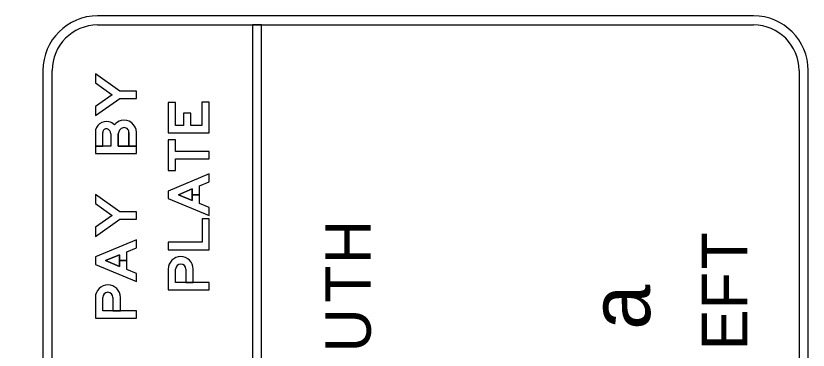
# Model space of a CAD drawing. Extents: x -830008.4 to -829992.7, y 1290284.1 to 1290294.4.
# Drawn here: x -829998.98 to -829998.11, y 1290293.064 to 1290293.43 of the extents above; entities that cross this region are included whole.
import ezdxf

# ---------------------------------------------------------------- set-up
doc = ezdxf.new("R2010")
doc.units = 0
doc.layers.add('SignPanel', color=7, linetype='Continuous')
doc.layers.add('TextLabel', color=7, linetype='Continuous')

msp = doc.modelspace()

# ---------------------------------------------------------------- linework, layer by layer
at = {"layer": 'SignPanel'}
for p, q in [((-829998.17015, 1290293.43038), (-829998.89015, 1290293.43038)), ((-829998.89015, 1290293.42038), (-829998.17015, 1290293.42038)), ((-829998.71015, 1290293.42038), (-829998.72015, 1290293.42038)), ((-829998.72015, 1290293.42038), (-829998.72015, 1290292.51038)), ((-829998.71015, 1290292.51038), (-829998.71015, 1290293.42038)), ((-829998.95015, 1290293.37038), (-829998.95015, 1290292.56038)), ((-829998.94015, 1290292.56038), (-829998.94015, 1290293.37038)), ((-829998.12015, 1290293.37038), (-829998.12015, 1290292.56048)), ((-829998.11015, 1290292.56048), (-829998.11015, 1290293.37038)), ((-829998.84765, 1290293.27947), (-829998.84765, 1290293.30265)), ((-829998.80455, 1290293.13798), (-829998.80455, 1290293.1526)), ((-829998.80455, 1290293.13798), (-829998.80455, 1290293.1526)), ((-829998.80455, 1290293.13798), (-829998.80455, 1290293.1526)), ((-829998.7852, 1290293.13798), (-829998.7852, 1290293.1526)), ((-829998.88455, 1290293.10698), (-829998.88455, 1290293.1216)), ((-829998.88455, 1290293.10698), (-829998.88455, 1290293.1216)), ((-829998.88455, 1290293.10698), (-829998.88455, 1290293.1216)), ((-829998.8652, 1290293.10698), (-829998.8652, 1290293.1216))]:
    msp.add_line(p, q, dxfattribs=at)
for points in [[(-829998.86588, 1290293.34798), (-829998.89265, 1290293.36688), (-829998.89265, 1290293.35696), (-829998.87419, 1290293.34393), (-829998.89265, 1290293.33089), (-829998.89265, 1290293.32098), (-829998.86588, 1290293.33988), (-829998.84765, 1290293.33988), (-829998.84765, 1290293.34798)], [(-829998.86588, 1290293.34798), (-829998.89265, 1290293.36688), (-829998.89265, 1290293.35696), (-829998.87419, 1290293.34393), (-829998.89265, 1290293.33089), (-829998.89265, 1290293.32098), (-829998.86588, 1290293.33988), (-829998.84765, 1290293.33988), (-829998.84765, 1290293.34798)], [(-829998.86588, 1290293.34798), (-829998.89265, 1290293.36688), (-829998.89265, 1290293.35696), (-829998.87419, 1290293.34393), (-829998.89265, 1290293.33089), (-829998.89265, 1290293.32098), (-829998.86588, 1290293.33988), (-829998.84765, 1290293.33988), (-829998.84765, 1290293.34798)], [(-829998.77575, 1290293.33588), (-829998.77575, 1290293.31023), (-829998.78786, 1290293.31023), (-829998.78786, 1290293.3235), (-829998.79596, 1290293.3235), (-829998.79596, 1290293.31023), (-829998.80455, 1290293.31023), (-829998.80455, 1290293.3352), (-829998.81265, 1290293.3352), (-829998.81265, 1290293.30213), (-829998.76765, 1290293.30213), (-829998.76765, 1290293.33588)], [(-829998.77575, 1290293.33588), (-829998.77575, 1290293.31023), (-829998.78786, 1290293.31023), (-829998.78786, 1290293.3235), (-829998.79596, 1290293.3235), (-829998.79596, 1290293.31023), (-829998.80455, 1290293.31023), (-829998.80455, 1290293.3352), (-829998.81265, 1290293.3352), (-829998.81265, 1290293.30213), (-829998.76765, 1290293.30213), (-829998.76765, 1290293.33588)], [(-829998.77575, 1290293.33588), (-829998.77575, 1290293.31023), (-829998.78786, 1290293.31023), (-829998.78786, 1290293.3235), (-829998.79596, 1290293.3235), (-829998.79596, 1290293.31023), (-829998.80455, 1290293.31023), (-829998.80455, 1290293.3352), (-829998.81265, 1290293.3352), (-829998.81265, 1290293.30213), (-829998.76765, 1290293.30213), (-829998.76765, 1290293.33588)], [(-829998.80455, 1290293.26076), (-829998.80455, 1290293.27358), (-829998.76765, 1290293.27358), (-829998.76765, 1290293.28168), (-829998.80455, 1290293.28168), (-829998.80455, 1290293.29451), (-829998.81265, 1290293.29451), (-829998.81265, 1290293.26076)], [(-829998.80455, 1290293.26076), (-829998.80455, 1290293.27358), (-829998.76765, 1290293.27358), (-829998.76765, 1290293.28168), (-829998.80455, 1290293.28168), (-829998.80455, 1290293.29451), (-829998.81265, 1290293.29451), (-829998.81265, 1290293.26076)], [(-829998.80455, 1290293.26076), (-829998.80455, 1290293.27358), (-829998.76765, 1290293.27358), (-829998.76765, 1290293.28168), (-829998.80455, 1290293.28168), (-829998.80455, 1290293.29451), (-829998.81265, 1290293.29451), (-829998.81265, 1290293.26076)], [(-829998.77823, 1290293.2245), (-829998.77823, 1290293.24395), (-829998.76765, 1290293.24839), (-829998.76765, 1290293.25718), (-829998.81265, 1290293.23828), (-829998.81265, 1290293.23018), (-829998.76765, 1290293.21128), (-829998.76765, 1290293.22006)], [(-829998.78633, 1290293.24055), (-829998.78633, 1290293.23423), (-829998.77823, 1290293.23423), (-829998.77823, 1290293.24395), (-829998.76765, 1290293.24839), (-829998.76765, 1290293.25718), (-829998.81265, 1290293.23828), (-829998.81265, 1290293.23018), (-829998.76765, 1290293.21128), (-829998.76765, 1290293.22006), (-829998.77823, 1290293.2245), (-829998.77823, 1290293.23423), (-829998.78633, 1290293.23423), (-829998.78633, 1290293.2279), (-829998.80138, 1290293.23423)], [(-829998.78633, 1290293.24055), (-829998.78633, 1290293.23423), (-829998.77823, 1290293.23423), (-829998.77823, 1290293.24395), (-829998.76765, 1290293.24839), (-829998.76765, 1290293.25718), (-829998.81265, 1290293.23828), (-829998.81265, 1290293.23018), (-829998.76765, 1290293.21128), (-829998.76765, 1290293.22006), (-829998.77823, 1290293.2245), (-829998.77823, 1290293.23423), (-829998.78633, 1290293.23423), (-829998.78633, 1290293.2279), (-829998.80138, 1290293.23423)], [(-829998.78633, 1290293.24055), (-829998.80138, 1290293.23423), (-829998.78633, 1290293.2279)], [(-829998.86588, 1290293.21557), (-829998.89265, 1290293.23447), (-829998.89265, 1290293.22456), (-829998.87419, 1290293.21152), (-829998.89265, 1290293.19849), (-829998.89265, 1290293.18857), (-829998.86588, 1290293.20747), (-829998.84765, 1290293.20747), (-829998.84765, 1290293.21557)], [(-829998.86588, 1290293.21557), (-829998.89265, 1290293.23447), (-829998.89265, 1290293.22456), (-829998.87419, 1290293.21152), (-829998.89265, 1290293.19849), (-829998.89265, 1290293.18857), (-829998.86588, 1290293.20747), (-829998.84765, 1290293.20747), (-829998.84765, 1290293.21557)], [(-829998.86588, 1290293.21557), (-829998.89265, 1290293.23447), (-829998.89265, 1290293.22456), (-829998.87419, 1290293.21152), (-829998.89265, 1290293.19849), (-829998.89265, 1290293.18857), (-829998.86588, 1290293.20747), (-829998.84765, 1290293.20747), (-829998.84765, 1290293.21557)], [(-829998.76765, 1290293.20769), (-829998.77553, 1290293.20769), (-829998.77553, 1290293.18204), (-829998.81265, 1290293.18204), (-829998.81265, 1290293.17394), (-829998.76765, 1290293.17394)], [(-829998.76765, 1290293.20769), (-829998.77553, 1290293.20769), (-829998.77553, 1290293.18204), (-829998.81265, 1290293.18204), (-829998.81265, 1290293.17394), (-829998.76765, 1290293.17394)], [(-829998.76765, 1290293.20769), (-829998.77553, 1290293.20769), (-829998.77553, 1290293.18204), (-829998.81265, 1290293.18204), (-829998.81265, 1290293.17394), (-829998.76765, 1290293.17394)], [(-829998.85823, 1290293.15223), (-829998.85823, 1290293.17167), (-829998.84765, 1290293.17611), (-829998.84765, 1290293.1849), (-829998.89265, 1290293.166), (-829998.89265, 1290293.1579), (-829998.84765, 1290293.139), (-829998.84765, 1290293.14779)], [(-829998.86633, 1290293.16827), (-829998.86633, 1290293.16195), (-829998.85823, 1290293.16195), (-829998.85823, 1290293.17167), (-829998.84765, 1290293.17611), (-829998.84765, 1290293.1849), (-829998.89265, 1290293.166), (-829998.89265, 1290293.1579), (-829998.84765, 1290293.139), (-829998.84765, 1290293.14779), (-829998.85823, 1290293.15223), (-829998.85823, 1290293.16195), (-829998.86633, 1290293.16195), (-829998.86633, 1290293.15563), (-829998.88138, 1290293.16195)], [(-829998.86633, 1290293.16827), (-829998.86633, 1290293.16195), (-829998.85823, 1290293.16195), (-829998.85823, 1290293.17167), (-829998.84765, 1290293.17611), (-829998.84765, 1290293.1849), (-829998.89265, 1290293.166), (-829998.89265, 1290293.1579), (-829998.84765, 1290293.139), (-829998.84765, 1290293.14779), (-829998.85823, 1290293.15223), (-829998.85823, 1290293.16195), (-829998.86633, 1290293.16195), (-829998.86633, 1290293.15563), (-829998.88138, 1290293.16195)], [(-829998.86633, 1290293.16827), (-829998.88138, 1290293.16195), (-829998.86633, 1290293.15563)]]:
    msp.add_lwpolyline(points, close=True, dxfattribs=at)
for points in [[(-829998.89265, 1290293.30265), (-829998.89265, 1290293.27947), (-829998.84765, 1290293.27947)], [(-829998.89265, 1290293.30265), (-829998.89265, 1290293.28758), (-829998.88455, 1290293.28758), (-829998.88455, 1290293.30265)], [(-829998.89265, 1290293.30265), (-829998.89265, 1290293.28758), (-829998.88455, 1290293.28758), (-829998.88455, 1290293.30265)], [(-829998.87555, 1290293.30091), (-829998.87555, 1290293.28757), (-829998.89265, 1290293.28757), (-829998.89265, 1290293.27947), (-829998.84765, 1290293.27947), (-829998.84765, 1290293.28757)], [(-829998.87555, 1290293.30091), (-829998.87555, 1290293.28757), (-829998.89265, 1290293.28757), (-829998.89265, 1290293.27947), (-829998.84765, 1290293.27947), (-829998.84765, 1290293.28757)], [(-829998.87555, 1290293.30091), (-829998.87555, 1290293.28757), (-829998.88455, 1290293.28757), (-829998.88455, 1290293.30265)], [(-829998.86745, 1290293.30091), (-829998.86745, 1290293.28757), (-829998.85575, 1290293.28757), (-829998.85575, 1290293.30265)], [(-829998.84765, 1290293.28757), (-829998.86745, 1290293.28757), (-829998.86745, 1290293.30091)], [(-829998.84765, 1290293.28757), (-829998.86745, 1290293.28757), (-829998.86745, 1290293.30091)], [(-829998.85575, 1290293.30265), (-829998.85575, 1290293.28758), (-829998.84765, 1290293.28758), (-829998.84765, 1290293.30265)], [(-829998.85575, 1290293.30265), (-829998.85575, 1290293.28758), (-829998.84765, 1290293.28758), (-829998.84765, 1290293.30265)], [(-829998.81265, 1290293.1526), (-829998.81265, 1290293.12988), (-829998.76765, 1290293.12988), (-829998.76765, 1290293.13798), (-829998.7852, 1290293.13798)], [(-829998.81265, 1290293.1526), (-829998.81265, 1290293.12988), (-829998.76765, 1290293.12988), (-829998.76765, 1290293.13798), (-829998.80455, 1290293.13798)], [(-829998.81265, 1290293.1526), (-829998.81265, 1290293.12988), (-829998.76765, 1290293.12988), (-829998.76765, 1290293.13798), (-829998.80455, 1290293.13798)], [(-829998.7933, 1290293.1526), (-829998.7933, 1290293.13798), (-829998.80455, 1290293.13798)], [(-829998.7933, 1290293.1526), (-829998.7933, 1290293.13798), (-829998.7852, 1290293.13798), (-829998.7852, 1290293.1526)], [(-829998.7933, 1290293.1526), (-829998.7933, 1290293.13798), (-829998.7852, 1290293.13798), (-829998.7852, 1290293.1526)], [(-829998.89265, 1290293.1216), (-829998.89265, 1290293.09888), (-829998.84765, 1290293.09888), (-829998.84765, 1290293.10698), (-829998.8652, 1290293.10698)], [(-829998.89265, 1290293.1216), (-829998.89265, 1290293.09888), (-829998.84765, 1290293.09888), (-829998.84765, 1290293.10698), (-829998.88455, 1290293.10698)], [(-829998.89265, 1290293.1216), (-829998.89265, 1290293.09888), (-829998.84765, 1290293.09888), (-829998.84765, 1290293.10698), (-829998.88455, 1290293.10698)], [(-829998.8733, 1290293.1216), (-829998.8733, 1290293.10698), (-829998.88455, 1290293.10698)], [(-829998.8733, 1290293.1216), (-829998.8733, 1290293.10698), (-829998.8652, 1290293.10698), (-829998.8652, 1290293.1216)], [(-829998.8733, 1290293.1216), (-829998.8733, 1290293.10698), (-829998.8652, 1290293.10698), (-829998.8652, 1290293.1216)]]:
    msp.add_lwpolyline(points, dxfattribs=at)
for centre, radius, start, end in [((-829998.89015, 1290293.37038), 0.06, 90, 180), ((-829998.17015, 1290293.37038), 0.06, 360, 90), ((-829998.89015, 1290293.37038), 0.05, 90, 180), ((-829998.17015, 1290293.37038), 0.05, 360, 90)]:
    msp.add_arc(centre, radius, start, end, dxfattribs=at)
for centre, major_axis, ratio, start_param, end_param in [((-829998.88073, 1290293.30265), (-0.01192, 0), 0.999999, 4.459709, 6.283185), ((-829998.88073, 1290293.30265), (-0.01192, 0), 0.999999, 4.459709, 6.283185), ((-829998.88073, 1290293.30265), (-0.01192, 0), 0.999999, 4.459709, 6.283185), ((-829998.86048, 1290293.30091), (-0.01507, 0), 0.999999, 4.965069, 5.558736), ((-829998.86048, 1290293.30091), (-0.01508, 0), 0.999999, 4.965069, 5.558736), ((-829998.86048, 1290293.30091), (-0.01507, 0), 0.999999, 4.965069, 5.558736), ((-829998.86093, 1290293.30265), (-0.01328, 0), 0.999999, 3.141593, 4.965069), ((-829998.86093, 1290293.30265), (-0.01328, 0), 0.999999, 3.141593, 4.965069), ((-829998.86093, 1290293.30265), (-0.01328, 0), 0.999999, 3.141593, 4.965069), ((-829998.88073, 1290293.30265), (-0.00382, 0), 0.999999, 4.459709, 6.283185), ((-829998.88073, 1290293.30265), (-0.00382, 0), 0.999999, 4.459709, 6.283185), ((-829998.88073, 1290293.30265), (-0.00382, 0), 0.999999, 4.459709, 6.283185), ((-829998.88118, 1290293.30091), (-0.00562, 0), 0.999999, 3.141593, 4.459709), ((-829998.88118, 1290293.30091), (-0.00563, 0), 0.999999, 3.141593, 4.459709), ((-829998.88118, 1290293.30091), (-0.00563, 0), 0.999999, 3.141593, 4.459709), ((-829998.88118, 1290293.30091), (-0.01373, 0), 0.999999, 3.95686, 4.459709), ((-829998.88118, 1290293.30091), (-0.01373, 0), 0.999999, 3.95686, 4.459709), ((-829998.88118, 1290293.30091), (-0.01373, 0), 0.999999, 3.95686, 4.459709), ((-829998.86048, 1290293.30091), (-0.00698, 0), 0.999999, 4.965069, 6.283185), ((-829998.86048, 1290293.30091), (-0.00698, 0), 0.999999, 4.965069, 6.283185), ((-829998.86048, 1290293.30091), (-0.00698, 0), 0.999999, 4.965069, 6.283185), ((-829998.86093, 1290293.30265), (-0.00517, 0), 0.999999, 3.141593, 4.965069), ((-829998.86093, 1290293.30265), (-0.00518, 0), 0.999999, 3.141593, 4.965069), ((-829998.86093, 1290293.30265), (-0.00518, 0), 0.999999, 3.141593, 4.965069), ((-829998.79893, 1290293.1526), (-0.01373, 0), 0.999995, 3.141593, 6.283185), ((-829998.79893, 1290293.1526), (-0.01373, 0), 0.999995, 3.141593, 6.283185), ((-829998.79893, 1290293.1526), (-0.01373, 0), 0.999995, 3.141593, 6.283185), ((-829998.79893, 1290293.1526), (-0.00562, 0), 0.999995, 3.141593, 6.283185), ((-829998.79893, 1290293.1526), (-0.00562, 0), 0.999995, 3.141593, 6.283185), ((-829998.79893, 1290293.1526), (-0.00562, 0), 0.999995, 3.141593, 6.283185), ((-829998.87893, 1290293.1216), (-0.01373, 0), 0.999995, 3.141593, 6.283185), ((-829998.87893, 1290293.1216), (-0.01373, 0), 0.999995, 3.141593, 6.283185), ((-829998.87893, 1290293.1216), (-0.01373, 0), 0.999995, 3.141593, 6.283185), ((-829998.87893, 1290293.1216), (-0.00562, 0), 0.999995, 3.141593, 6.283185), ((-829998.87893, 1290293.1216), (-0.00562, 0), 0.999995, 3.141593, 6.283185), ((-829998.87893, 1290293.1216), (-0.00562, 0), 0.999995, 3.141593, 6.283185)]:
    msp.add_ellipse(centre, major_axis=major_axis, ratio=ratio, start_param=start_param, end_param=end_param, dxfattribs=at)
at = {"layer": 'TextLabel'}
msp.add_arc((-829995.62331, 1290293.6404), 3.97527, 185.30621, 226.07069, dxfattribs=at)

# ---------------------------------------------------------------- texts
at = {"layer": 'SignPanel'}
for s, height, p in [('H', 0.05, (-829998.59032, 1290293.15815)), ('T', 0.05, (-829998.1769, 1290293.15221)), ('T', 0.05, (-829998.59032, 1290293.1157)), ('F', 0.05, (-829998.1769, 1290293.10861)), ('a', 0.0665, (-829998.28367, 1290293.08621)), ('U', 0.05, (-829998.59032, 1290293.06135)), ('E', 0.05, (-829998.1769, 1290293.06376))]:
    msp.add_text(s, height=height, rotation=90, dxfattribs=at).set_placement(p)

doc.saveas('drawing.dxf')
